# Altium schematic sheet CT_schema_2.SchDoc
size 400 x 230 mm
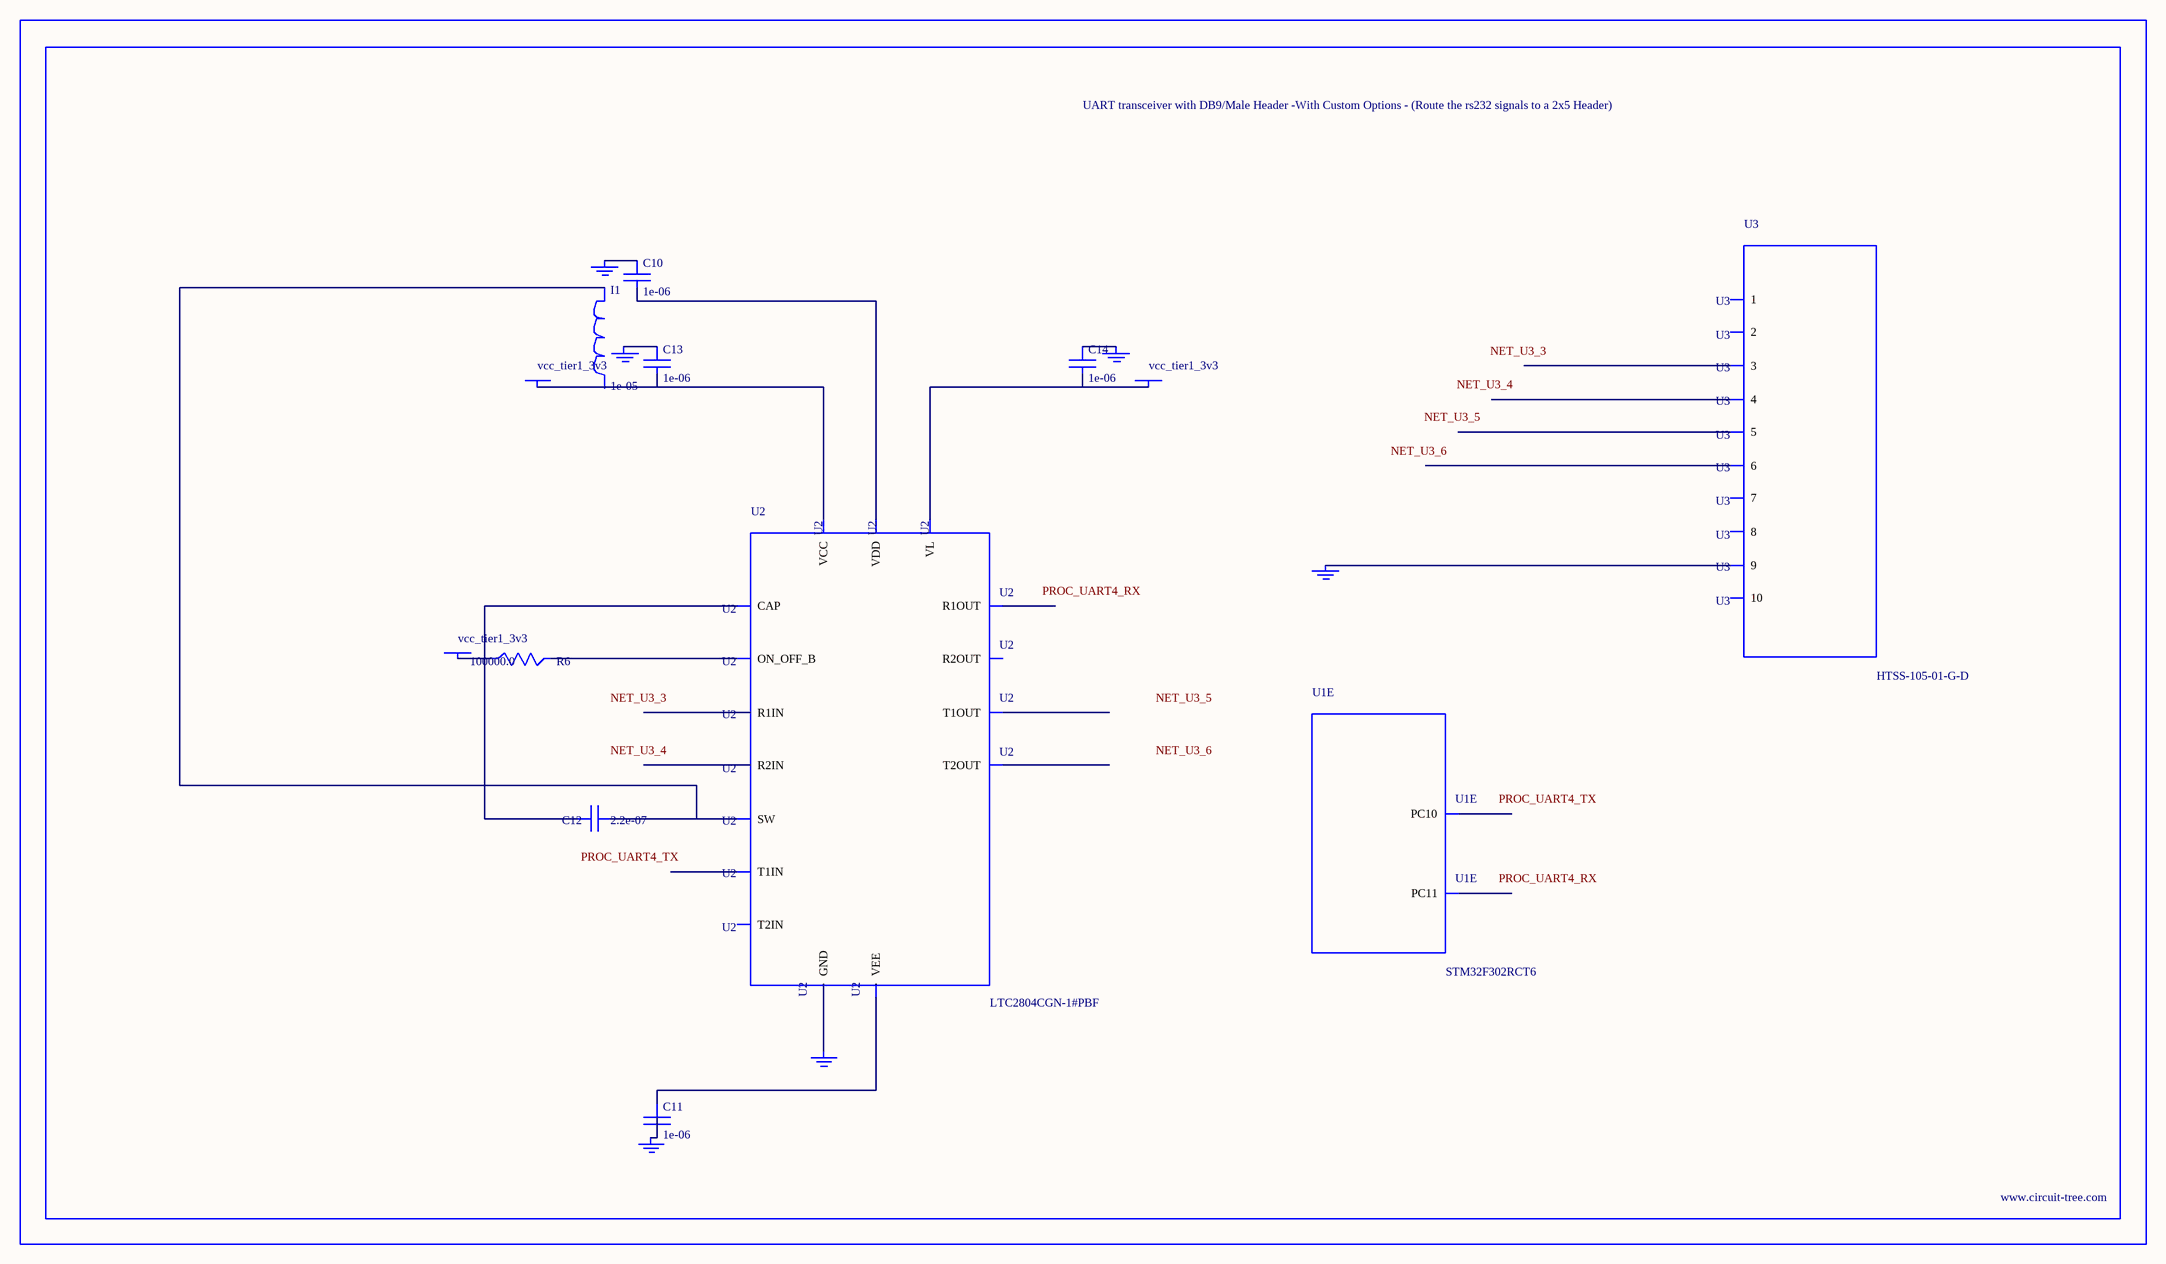
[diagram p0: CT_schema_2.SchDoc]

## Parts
BORDER1  (no value)
C10  1e-06  [C0603]
C11  1e-06  [C0603]
C12  2.2e-07  [C0603]
C13  1e-06  [C0603]
C14  1e-06  [C0603]
GND_INSTANCE_1_0  (no value)
GND_INSTANCE_1_1  (no value)
GND_INSTANCE_1_2  (no value)
GND_INSTANCE_1_3  (no value)
GND_INSTANCE_1_4  (no value)
GND_INSTANCE_1_5  (no value)
I1  1e-05  [L1210]
POWER_INSTANCE_1_0  vcc_tier1_3v3
POWER_INSTANCE_1_1  vcc_tier1_3v3
POWER_INSTANCE_1_2  vcc_tier1_3v3
R6  100000.0  [R0603]
U1  STM32F302RCT6  [LQFP64]  (part E of 8)
U2  LTC2804CGN-1#PBF  [SSOP-16]
U3  HTSS-105-01-G-D  [HTSS-105-01-G-D]

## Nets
NetC10_1: C10.1 GND_INSTANCE_1_1.0(GND)
NetC10_2: C10.2 U2.6(VDD)
NetC11_1: C11.1 U2.9(VEE)
NetC11_2: C11.2 GND_INSTANCE_1_2.0(GND)
NetC12_1: C12.1 I1.1 U2.7(SW)
NetC12_2: C12.2 U2.10(CAP)
NetC13_1: C13.1 GND_INSTANCE_1_0.0(GND)
NetC13_2: C13.2 POWER_INSTANCE_1_0.0(PWR) U2.5(VCC)
NetC14_1: C14.1 GND_INSTANCE_1_3.0(GND)
NetC14_2: C14.2 POWER_INSTANCE_1_2.0(PWR) U2.12(VL)
NetGND_INSTANCE_1_4_0: GND_INSTANCE_1_4.0(GND) U2.8(GND)
NetGND_INSTANCE_1_5_0: GND_INSTANCE_1_5.0(GND) U3.9
NetPOWER_INSTANCE_1_1_0: POWER_INSTANCE_1_1.0(PWR) R6.1
NetR6_2: R6.2 U2.11(ON_OFF_B)

Not connected (* = marked no-connect by the designer): I1 2; U1 51(PC10) 52(PC11); U2 1(R1IN) 2(R2IN) 3(T1OUT) 4(T2OUT) 13(T2IN) 14(T1IN) 15(R2OUT) 16(R1OUT); U3 1 2 3 4 5 6 7 8 10

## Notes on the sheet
- Labels drawn without touching a wire or pin: NET_U3_3, NET_U3_4, NET_U3_5, NET_U3_6, PROC_UART4_RX, PROC_UART4_TX

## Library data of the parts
BORDER1 = BORDER_PAGE1
C10 C11 C13 C14 = C0603C105K3RACTU
C12 = C0603C224K3RAC
GND_INSTANCE_1_0-GND_INSTANCE_1_5 = GND
I1 = CBC3225T100MR
POWER_INSTANCE_1_0-POWER_INSTANCE_1_2 = PWR
R6 = RC0603JR-07100KL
